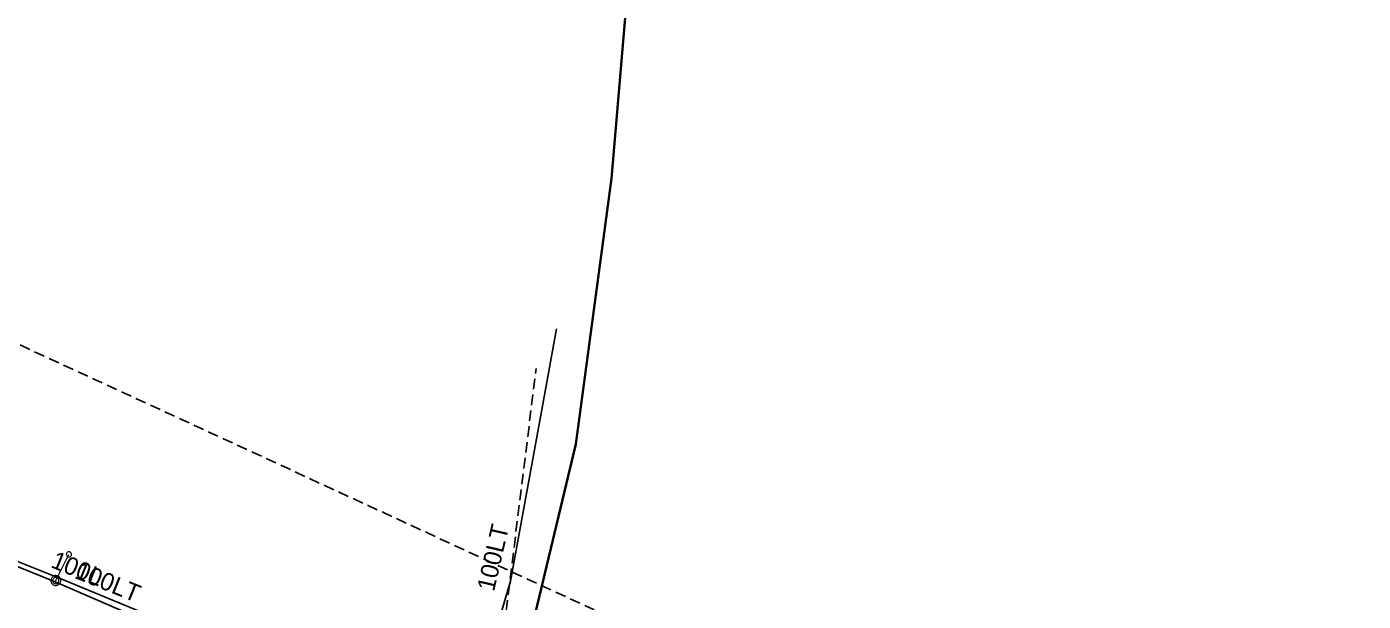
# Model space of a CAD drawing. Extents: x -735085 to -733500, y -1044153 to -1043402.
# Drawn here: x -734712.5 to -734591.8, y -1043571.5 to -1043519.6 of the extents above; entities that cross this region are included whole.
import ezdxf

# ---------------------------------------------------------------- set-up
doc = ezdxf.new("R2010")
doc.units = 0
doc.header["$LTSCALE"] = 0.32
doc.linetypes.add('MEDIUM_DASHED', pattern=[4.5, 3, -1.5])
doc.layers.add('15', color=7, linetype='Continuous')
doc.layers.add('63', color=7, linetype='MEDIUM_DASHED', lineweight=25)
doc.layers.add('8', color=7, linetype='Continuous', lineweight=13)

msp = doc.modelspace()

# ---------------------------------------------------------------- linework, layer by layer
at = {"layer": '63'}
msp.add_lwpolyline([(-734796.022, -1043808.279), (-734957.658, -1043641.023), (-734957.66, -1043641.021), (-735032.487, -1043496.398), (-735032.488, -1043496.396), (-735032.488, -1043496.394), (-735032.488, -1043496.393), (-735032.488, -1043496.391), (-735014.686, -1043433.916), (-735014.686, -1043433.914), (-735014.685, -1043433.913), (-735014.683, -1043433.911), (-735014.682, -1043433.91), (-735014.68, -1043433.909), (-735014.678, -1043433.909), (-735014.676, -1043433.909), (-734957.569, -1043435.5), (-734957.567, -1043435.5), (-734957.565, -1043435.501), (-734250.468, -1043761.931)], dxfattribs=at)
at = {"layer": '8', "lineweight": 35}
msp.add_lwpolyline([(-734650.57, -1043435.42), (-734654.39, -1043471.32), (-734659.68, -1043533.32), (-734662.879, -1043557.32), (-734667.76, -1043577.7)], dxfattribs=at)
at = {"layer": '8', "lineweight": 25}
for points in [[(-734792.71, -1043535.18), (-734782.352, -1043539.852), (-734773.644, -1043543.536), (-734767.807, -1043545.587), (-734738.734, -1043557.836), (-734732.528, -1043560.258), (-734709.46, -1043569.477), (-734674.151, -1043584.087)], [(-734664.64, -1043546.91), (-734665.87, -1043553.7), (-734668.78, -1043569.71), (-734670.039, -1043573.91), (-734670.289, -1043574.67)], [(-734737.059, -1043558.35), (-734732.69, -1043560.26), (-734714.53, -1043567.89), (-734709.92, -1043569.78), (-734695.94, -1043575.82), (-734676.559, -1043583.89)]]:
    msp.add_lwpolyline(points, dxfattribs=at)
at = {"layer": '8', "linetype": 'MEDIUM_DASHED', "lineweight": 25}
msp.add_lwpolyline([(-734671.028, -1043578.02), (-734669.353, -1043573.811), (-734666.474, -1043550.485)], dxfattribs=at)
at = {"layer": '8'}
msp.add_lwpolyline([(-734709.92, -1043569.78), (-734709.85, -1043569.66), (-734708.67, -1043567.29)], dxfattribs=at)
for points in [[(-734708.599, -1043567.069), (-734708.65, -1043567.057), (-734708.703, -1043567.056), (-734708.754, -1043567.067), (-734708.802, -1043567.09), (-734708.843, -1043567.123), (-734708.875, -1043567.164), (-734708.898, -1043567.211), (-734708.91, -1043567.262), (-734708.909, -1043567.315), (-734708.896, -1043567.366), (-734708.872, -1043567.413), (-734708.838, -1043567.453), (-734708.796, -1043567.485), (-734708.748, -1043567.506), (-734708.697, -1043567.516), (-734708.644, -1043567.513), (-734708.594, -1043567.5), (-734708.547, -1043567.475), (-734708.508, -1043567.44), (-734708.477, -1043567.397), (-734708.457, -1043567.349), (-734708.449, -1043567.297), (-734708.453, -1043567.244), (-734708.468, -1043567.194), (-734708.494, -1043567.149), (-734708.53, -1043567.11), (-734708.573, -1043567.081)], [(-734709.703, -1043569.237), (-734709.773, -1043569.217), (-734709.846, -1043569.209), (-734709.919, -1043569.213), (-734709.99, -1043569.229), (-734710.059, -1043569.256), (-734710.121, -1043569.293), (-734710.176, -1043569.341), (-734710.224, -1043569.397), (-734710.261, -1043569.46), (-734710.288, -1043569.528), (-734710.303, -1043569.6), (-734710.306, -1043569.673), (-734710.297, -1043569.745), (-734710.277, -1043569.816), (-734710.245, -1043569.882), (-734710.203, -1043569.941), (-734710.151, -1043569.994), (-734710.093, -1043570.037), (-734710.027, -1043570.07), (-734709.958, -1043570.092), (-734709.885, -1043570.102), (-734709.812, -1043570.101), (-734709.74, -1043570.087), (-734709.672, -1043570.061), (-734709.608, -1043570.025), (-734709.551, -1043569.979), (-734709.502, -1043569.925), (-734709.463, -1043569.863), (-734709.434, -1043569.796), (-734709.417, -1043569.724), (-734709.412, -1043569.651), (-734709.419, -1043569.578), (-734709.437, -1043569.507), (-734709.467, -1043569.441), (-734709.508, -1043569.379), (-734709.557, -1043569.326), (-734709.616, -1043569.281), (-734709.68, -1043569.247)], [(-734709.759, -1043569.388), (-734709.815, -1043569.373), (-734709.874, -1043569.37), (-734709.932, -1043569.379), (-734709.987, -1043569.4), (-734710.037, -1043569.43), (-734710.079, -1043569.471), (-734710.112, -1043569.52), (-734710.134, -1043569.574), (-734710.145, -1043569.631), (-734710.143, -1043569.69), (-734710.131, -1043569.748), (-734710.107, -1043569.8), (-734710.072, -1043569.847), (-734710.028, -1043569.887), (-734709.978, -1043569.917), (-734709.922, -1043569.935), (-734709.864, -1043569.942), (-734709.806, -1043569.938), (-734709.75, -1043569.92), (-734709.698, -1043569.892), (-734709.654, -1043569.854), (-734709.617, -1043569.808), (-734709.591, -1043569.756), (-734709.577, -1043569.7), (-734709.573, -1043569.641), (-734709.582, -1043569.583), (-734709.603, -1043569.528), (-734709.634, -1043569.48), (-734709.675, -1043569.438), (-734709.724, -1043569.404)]]:
    msp.add_lwpolyline(points, close=True, dxfattribs=at)

# ---------------------------------------------------------------- texts
at = {"layer": '15'}
for s, rotation, p in [('100LT ', 77, (-734670.281, -1043570.711)), ('100L', 338, (-734710.404, -1043568.424)), ('100LT ', 338, (-734708.26, -1043569.393))]:
    msp.add_text(s, height=1.6, rotation=rotation, dxfattribs=at).set_placement(p)

doc.saveas('drawing.dxf')
